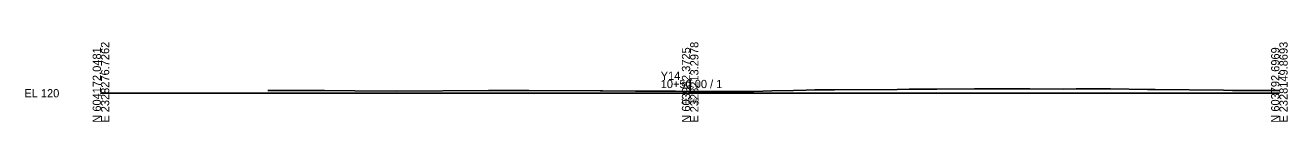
# Model space of a CAD drawing. Extents: x -26 to 2328312, y 990 to 603967.
# Drawn here: x -25.7 to 402.8, y 990.3 to 1017.3 of the extents above; entities that cross this region are included whole.
import ezdxf

# ---------------------------------------------------------------- set-up
doc = ezdxf.new("R2010")
doc.units = 0
for name, color, linetype in [('Default', 7, 'Continuous'), ('Exist Cross Section Cell', 7, 'Continuous'), ('Exist XS Center Line Elevation Label', 7, 'Continuous'), ('Exist XS Ground Line', 7, 'Continuous')]:
    doc.layers.add(name, color=color, linetype=linetype)

msp = doc.modelspace()

# ---------------------------------------------------------------- linework, layer by layer
at = {"layer": 'Exist Cross Section Cell'}
for p, q in [((200, 1000), (200, 1004.54)), ((0, 1000), (200, 1000)), ((200, 1000), (400, 1000))]:
    msp.add_line(p, q, dxfattribs=at)
at = {"layer": 'Exist XS Ground Line'}
msp.add_lwpolyline([(56.69, 1000.95), (59.59, 1000.96), (71.43, 1000.98), (75.93, 1000.93), (86.18, 1000.8), (100.48, 1000.69), (131.5, 1000.9), (133.65, 1000.9), (138.44, 1000.89), (145.26, 1000.88), (169.41, 1000.82), (170.39, 1000.82), (181.47, 1000.71), (185.86, 1000.67), (187.08, 1000.66), (187.55, 1000.65), (188.51, 1000.65), (194.99, 1000.65), (200, 1000.62), (202.17, 1000.61), (206.74, 1000.61), (217.48, 1000.54), (221.56, 1000.61), (227.71, 1000.79), (235.13, 1000.94), (239.41, 1001.04), (242.35, 1001.1), (245.26, 1001.13), (248.56, 1001.15), (248.99, 1001.13), (270.3, 1001.3), (274.35, 1001.33), (283.74, 1001.4), (296.53, 1001.51), (315.24, 1001.48), (326.7, 1001.42), (330.98, 1001.46), (338.28, 1001.45), (339.49, 1001.48), (340.93, 1001.46), (342.06, 1001.45), (342.66, 1001.45), (355.25, 1001.29), (357.48, 1001.3), (357.8, 1001.25), (381.03, 1001), (384.12, 1000.96), (385.02, 1000.96), (391.1, 1000.98), (400, 1000.9)], dxfattribs=at)

# ---------------------------------------------------------------- texts
at = {"layer": 'Default'}
msp.add_text('-', height=1.5, dxfattribs=at).set_placement((-0.37, 999.25))
at = {"layer": 'Exist Cross Section Cell'}
for s, p in [('E 2328276.7262', (2.8, 990)), ('E 2328213.2978', (202.8, 990)), ('E 2328149.8693', (402.8, 990)), ('N 604172.0481', (0, 990)), ('N 603982.3725', (200, 990)), ('N 603792.6969', (400, 990))]:
    msp.add_text(s, height=2.8, rotation=90, dxfattribs=at).set_placement(p)
for s, p in [('Y14', (190, 1004.54)), ('10+50.00 / 1', (190, 1001.74)), ('EL 120', (-26, 998.6))]:
    msp.add_text(s, height=2.8, dxfattribs=at).set_placement(p)
at = {"layer": 'Exist XS Center Line Elevation Label'}
msp.add_text('120.62', height=1.5, dxfattribs=at).set_placement((196.85, 996.62))

doc.saveas('drawing.dxf')
